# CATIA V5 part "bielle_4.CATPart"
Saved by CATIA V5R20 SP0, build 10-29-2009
Part number: sqlt_bielle_4
Publications: "épaisseur_piece", "longueur_bielle_4", "rayon_pivot_bielle", "Plan.1", "Point.1", "Droite.1", "Point.2", "Point.4", "Point.5", "Droite.2", "Droite.3", "Plan.2", "Plan.3", "Plan.4", "Point.6", "Point.7", "Point.8"
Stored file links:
  D:\ecole\thinkmotion\IAO\bielle_4.CATPart
  D:\ecole\thinkmotion\IAO\bielle_1.CATPart
  D:\ecole\thinkmotion\IAO\sqlt mecanisme coulisseau.CATProduct
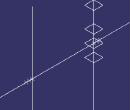
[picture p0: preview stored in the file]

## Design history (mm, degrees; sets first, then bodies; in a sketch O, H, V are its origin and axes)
Parameters
  `épaisseur_piece` = 20 mm {= `External.épaisseur_piece`}
  longueur_bielle_4 = 100 mm {= External.longueur_bielle_4}
  rayon_pivot_bielle = 5 mm {= External.rayon_pivot_bielle}
External parameters (linked from other documents)
  `External.épaisseur_piece` = 20 mm
  External.longueur_bielle_4 = 100 mm
  External.rayon_pivot_bielle = 5 mm
Set1 "sqlt_bielle_4"
  Plane1: type Offset, RefPlane xy-plane, Offset 0
  Point1: (0, 0, 0)
  Line1: type PtDir, RefPoint Point1, Direction yz-plane, Start 0, End 20
  Point2: type OnCurve, Support Line1, Length 100 {= longueur_bielle_4}
  Point3: (10 {= rayon_pivot_bielle +5mm}, 0, 0), relative to Point2
  Line2: type PtDir, RefPoint Point1, Direction Plane1, Start 0, End 20
  Line3: type PtDir, RefPoint Point2, Direction Plane1, Start 0, End 20
  Plane2: type Offset, RefPlane xy-plane, Offset 20 {= `épaisseur_piece`}
  Plane3: type Offset, RefPlane xy-plane, Offset 20 {= `épaisseur_piece`}, reversed
  Plane4: type Offset, RefPlane xy-plane, Offset 53.3333 {= 3*`épaisseur_piece` -1/3*`épaisseur_piece`}
  Point4: (-5 {= -rayon_pivot_bielle}, 0, 0)
  Point5: (-10 {= -rayon_pivot_bielle -5mm}, 0, 0)
  Point6: (5 {= rayon_pivot_bielle}, 0, 0), relative to Point2
Body1 (main body)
